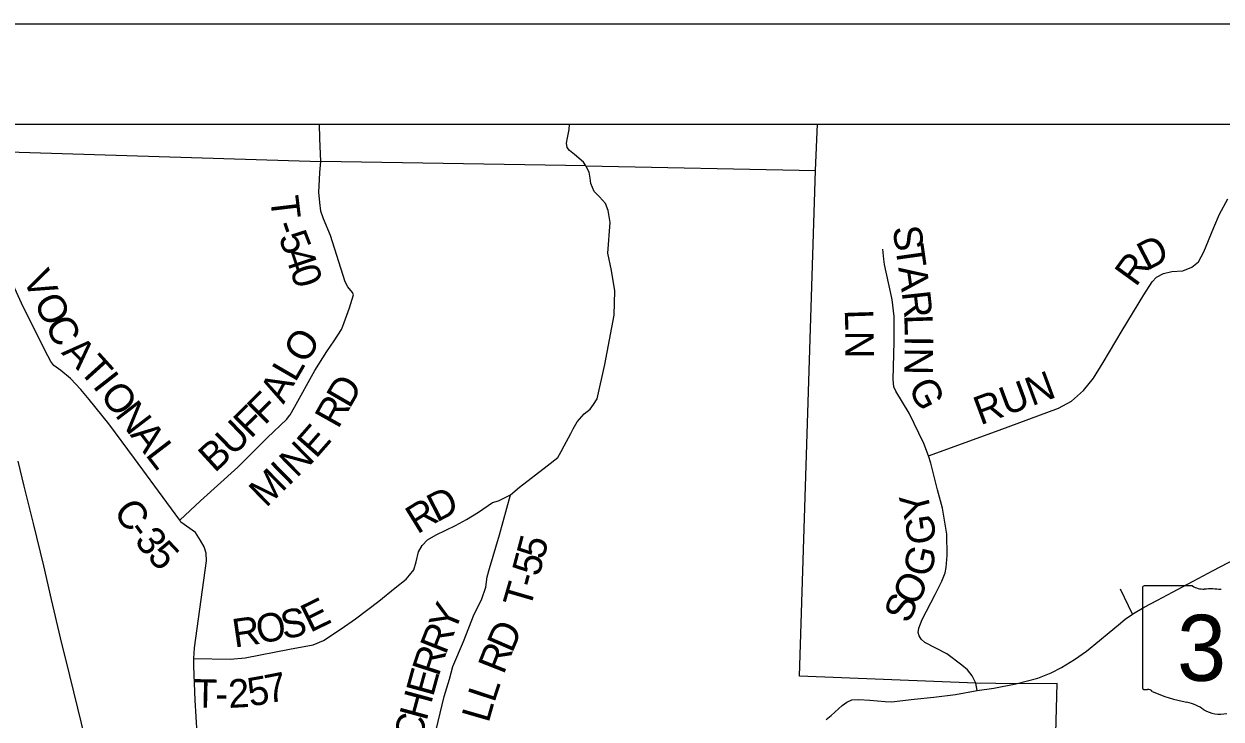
# Model space of a CAD drawing. Extents: x -22 to 431, y -18 to 160.
# Drawn here: x 324.836 to 327.228, y 158.732 to 160.12 of the extents above; entities that cross this region are included whole.
import ezdxf

# ---------------------------------------------------------------- set-up
doc = ezdxf.new("R2010")
doc.units = 0
for name, color, linetype in [('GM_X_Adjacent_County_Text', 7, 'Continuous'), ('GM_X_Airport_Location_Class_2', 7, 'Continuous'), ('GM_X_City_Street', 7, 'Continuous'), ('GM_X_City_Street_Text', 7, 'Continuous'), ('GM_X_County_ROW', 7, 'Continuous'), ('GM_X_Major_River_Text', 7, 'Continuous'), ('GM_X_Minor_River_Text', 7, 'Continuous'), ('GM_X_Rail_Line', 7, 'Continuous'), ('GM_X_Section', 7, 'Continuous')]:
    doc.layers.add(name, color=color, linetype=linetype)

msp = doc.modelspace()

# ---------------------------------------------------------------- linework, layer by layer
at = {"layer": 'GM_X_Adjacent_County_Text'}
for points in [[(325.1477, 159.1289), (325.1213, 159.1641), (325.057, 159.252), (325.0057, 159.3213), (324.9662, 159.3699), (324.9498, 159.3902), (324.9293, 159.4116), (324.9095, 159.4278), (324.896, 159.4378), (324.8897, 159.4458), (324.8837, 159.4573), (324.8346, 159.5549), (324.8044, 159.6209), (324.7775, 159.6781), (324.7754, 159.6876), (324.7699, 159.7066), (324.7645, 159.7613), (324.7657, 159.7999), (324.7685, 159.8633)], [(325.2014, 158.1784), (325.2032, 158.2202), (325.2052, 158.2656), (325.2047, 158.3058), (325.2054, 158.3188), (325.2013, 158.3826), (325.196, 158.4523), (325.1937, 158.5182), (325.1897, 158.5964), (325.1838, 158.6696), (325.1784, 158.7696), (325.1754, 158.8374), (325.1757, 158.8531), (325.1766, 158.8743), (325.2008, 159.0478), (325.2, 159.063), (325.1962, 159.0756), (325.189, 159.0885), (325.1787, 159.1045), (325.1495, 159.1247), (325.1477, 159.1289)]]:
    msp.add_lwpolyline(points, dxfattribs=at)
at = {"layer": 'GM_X_Airport_Location_Class_2'}
for p, q in [((327.0707, 158.9942), (327.0707, 158.7941)), ((327.1705, 158.9977), (327.074, 158.9977))]:
    msp.add_line(p, q, dxfattribs=at)
for centre, major_axis, start_param, end_param in [((327.0745, 158.9947), (0.00382, 0), 1.712693, 3.28349), ((327.1935, 159.0209), (0.037, 0), 4.042523, 4.731795), ((327.2058, 158.8853), (0.133, 0), 1.404758, 1.657858), ((327.0745, 158.7937), (0.00385, 0), 3.00124, 4.508301), ((327.0751, 158.8141), (0.0294, 0), 4.665946, 4.897461), ((327.0811, 158.7826), (0.0106, 0), 0.519207, 1.627899), ((327.215, 158.9624), (0.2524, 0), 4.195997, 4.488961), ((327.1397, 158.7042), (0.079, 0), 0.823519, 1.323587), ((327.2251, 158.7816), (0.0501, 0), 4.026481, 4.996735)]:
    msp.add_ellipse(centre, major_axis=major_axis, ratio=0.8, start_param=start_param, end_param=end_param, dxfattribs=at)
at = {"layer": 'GM_X_County_ROW'}
msp.add_lwpolyline([(326.4388, 158.7307), (326.4488, 158.7388), (326.4707, 158.7588), (326.48, 158.7658), (326.4898, 158.7701), (326.5039, 158.7708), (326.5259, 158.7696), (326.5567, 158.7667), (326.57, 158.7661), (326.5859, 158.7683), (326.6143, 158.7714), (326.6537, 158.7755), (326.6972, 158.7808), (326.7405, 158.7888), (326.7735, 158.7934), (326.8175, 158.8019), (326.8618, 158.8135), (326.8882, 158.8242), (326.9088, 158.8347), (326.9351, 158.8511), (326.9588, 158.8675), (326.985, 158.8888), (327.0044, 158.9047), (327.0228, 158.9202), (327.0359, 158.931), (327.0507, 158.9411), (327.0531, 158.9427), (327.0738, 158.9552), (327.1009, 158.969), (327.1309, 158.9854), (327.1723, 159.007), (327.2118, 159.0285), (327.2566, 159.0517)], dxfattribs=at)
at = {"layer": 'GM_X_Major_River_Text'}
for p, q in [((326.4177, 159.8276), (326.4213, 159.9199)), ((324.7687, 159.8658), (325.4291, 159.8451)), ((325.9586, 159.8363), (325.4291, 159.8451)), ((325.9586, 159.8363), (326.4177, 159.8276)), ((326.3856, 158.8174), (326.4177, 159.8276)), ((326.7375, 158.8037), (326.3856, 158.8174)), ((326.8175, 158.8019), (326.7375, 158.8037)), ((326.9, 158.8029), (326.8175, 158.8019)), ((326.869, 157.4312), (326.9, 158.8029))]:
    msp.add_line(p, q, dxfattribs=at)
at = {"layer": 'GM_X_Minor_River_Text'}
for points in [[(325.4274, 159.8231), (325.4291, 159.8451), (325.4271, 159.8915), (325.4267, 159.9199)], [(325.9244, 159.9061), (325.9251, 159.9094), (325.926, 159.9199)], [(325.9156, 159.2774), (325.9288, 159.3022), (325.9331, 159.3113), (325.9415, 159.3257), (325.9555, 159.3411), (325.9674, 159.3507), (325.9742, 159.3598), (325.981, 159.3716), (325.9969, 159.4398), (326.0151, 159.5381), (326.0169, 159.5867), (326.0099, 159.6277), (326.0026, 159.6622), (326.0071, 159.7232), (326.0035, 159.7477), (325.9981, 159.7614), (325.9862, 159.775), (325.9754, 159.7853), (325.9688, 159.801), (325.9674, 159.8118), (325.9652, 159.8242), (325.9586, 159.8363), (325.954, 159.8439), (325.9357, 159.8591), (325.9257, 159.8674), (325.9211, 159.8735), (325.9202, 159.882), (325.9217, 159.8924), (325.9244, 159.9061)], [(325.3675, 159.3392), (325.3677, 159.3395), (325.3765, 159.3548), (325.417, 159.4282), (325.441, 159.4658), (325.4556, 159.4874), (325.4706, 159.5099), (325.4733, 159.5167), (325.4863, 159.5528), (325.4942, 159.5789), (325.4923, 159.5839), (325.4832, 159.5952), (325.4775, 159.605), (325.4486, 159.6978), (325.4346, 159.7307), (325.429, 159.7458), (325.4275, 159.7632), (325.4252, 159.7843), (325.4263, 159.8096), (325.4274, 159.8231)], [(326.7405, 158.7888), (326.7375, 158.8037), (326.7305, 158.818), (326.721, 158.8301), (326.7101, 158.8392), (326.6801, 158.8624), (326.6361, 158.8845), (326.6286, 158.8911), (326.6245, 158.8979), (326.6227, 158.9048), (326.6239, 158.9131), (326.6309, 158.9309), (326.6567, 158.9803), (326.6698, 159.0071), (326.6764, 159.0241), (326.6788, 159.0347), (326.6805, 159.0586), (326.6798, 159.1011), (326.6712, 159.1532), (326.6609, 159.1893), (326.6478, 159.243), (326.643, 159.2578), (326.7843, 159.3088), (326.9032, 159.3528), (326.9287, 159.3665), (326.9531, 159.3879), (326.9727, 159.4128), (326.9923, 159.4441), (327.0303, 159.5075), (327.0734, 159.5788), (327.0899, 159.6048), (327.0987, 159.6142), (327.1128, 159.6217), (327.1291, 159.6257), (327.1511, 159.627), (327.1693, 159.634), (327.183, 159.6452), (327.1931, 159.6649), (327.2132, 159.7136), (327.2248, 159.7401), (327.2414, 159.7707)], [(326.643, 159.2578), (326.6338, 159.2822), (326.6044, 159.3425), (326.5779, 159.3868), (326.5738, 159.3951), (326.5728, 159.4096), (326.5747, 159.4851), (326.5747, 159.5356), (326.5705, 159.5698), (326.5585, 159.6242), (326.5556, 159.6398), (326.5538, 159.65), (326.5521, 159.6702)], [(325.1477, 159.1289), (325.1891, 159.1673), (325.2636, 159.235), (325.3219, 159.2932), (325.3611, 159.3305), (325.3667, 159.3378), (325.3675, 159.3392)], [(325.6257, 158.5856), (325.6274, 158.5922), (325.6327, 158.6116), (325.6594, 158.7102), (325.6757, 158.7766), (325.686, 158.8114), (325.6926, 158.8365), (325.7141, 158.8867), (325.7356, 158.9415), (325.75, 158.9697), (325.7587, 158.9953), (325.7618, 159.0158), (325.7659, 159.0327), (325.7862, 159.1), (325.8084, 159.1795), (325.8259, 159.1952), (325.8817, 159.2373), (325.9028, 159.2543), (325.9094, 159.2659), (325.9156, 159.2774)], [(325.1757, 158.8531), (325.248, 158.8517), (325.2783, 158.854), (325.3663, 158.8713), (325.4139, 158.8802), (325.4342, 158.8889), (325.4696, 158.9118), (325.4986, 158.9323), (325.5448, 158.9673), (325.5776, 158.9936), (325.5995, 159.0112), (325.6066, 159.0189), (325.6148, 159.0301), (325.6194, 159.046), (325.624, 159.0655), (325.6317, 159.0783), (325.642, 159.0895), (325.6599, 159.0998), (325.6984, 159.1182), (325.7205, 159.1305), (325.7439, 159.1447), (325.7723, 159.164), (325.7841, 159.1673), (325.8084, 159.1795)], [(327.0507, 158.9411), (327.0271, 158.9914)]]:
    msp.add_lwpolyline(points, dxfattribs=at)
at = {"layer": 'GM_X_Rail_Line'}
msp.add_lwpolyline([(325.0236, 158.268), (325.0178, 158.3353), (325.0111, 158.3892), (325.0083, 158.4105), (325.0062, 158.4257), (324.9949, 158.5051), (324.9839, 158.5695), (324.9706, 158.6339), (324.9581, 158.6937), (324.9437, 158.7535), (324.9274, 158.819), (324.909, 158.8939), (324.8914, 158.9704), (324.8757, 159.0378), (324.855, 159.1222), (324.8366, 159.1967), (324.8245, 159.247)], dxfattribs=at)
at = {"layer": 'GM_X_Section'}
msp.add_line((319.5549, 159.9199), (331.7949, 159.9199), dxfattribs=at)
msp.add_lwpolyline([(319.3549, 160.1199), (331.9949, 160.1199), (331.9949, 147.4799), (319.3549, 147.4799)], close=True, dxfattribs=at)

# ---------------------------------------------------------------- texts
at = {"layer": 'GM_X_Airport_Location_Class_2'}
msp.add_text('313', height=0.13184, dxfattribs=at).set_placement((327.1398, 158.8082))
at = {"layer": 'GM_X_City_Street'}
for s, rotation, p in [('V', 294.5617, (324.833, 159.6124)), ('O', 296.2146, (324.8546, 159.5653)), ('C', 296.7147, (324.8769, 159.5199)), ('A', 314.6749, (324.9092, 159.4625)), ('T', 312.1791, (324.9439, 159.4274)), ('I', 308.0588, (324.9717, 159.3968)), ('O', 307.4906, (324.986, 159.3785)), ('N', 307.4491, (325.0165, 159.3389)), ('A', 307.4477, (325.0469, 159.2992)), ('L', 307.4493, (325.0773, 159.2595)), ('C', 305.6357, (325.013, 159.1461)), ('-', 306.0104, (325.0404, 159.1079)), ('3', 307.5967, (325.0552, 159.0876)), ('5', 313.2597, (325.0805, 159.0552))]:
    msp.add_text(s, height=0.0568, rotation=rotation, dxfattribs=at).set_placement(p)
at = {"layer": 'GM_X_City_Street_Text'}
for s, height, rotation, p in [('T', 0.0568, 276.7915, (325.3276, 159.7734)), ('-', 0.0568, 288.9884, (325.3355, 159.7184)), ('5', 0.0568, 291.0715, (325.3439, 159.6942)), ('S', 0.0568, 278.114, (326.5713, 159.7135)), ('D', 0.0568, 27.4415, (327.0796, 159.6265)), ('T', 0.0568, 278.1141, (326.5767, 159.6756)), ('4', 0.0568, 288.3543, (325.3562, 159.6622)), ('R', 0.0568, 54.1055, (327.0575, 159.5932)), ('0', 0.0568, 287.5883, (325.3672, 159.6292)), ('A', 0.0568, 278.0884, (326.5827, 159.6335)), ('R', 0.0568, 276.1984, (326.5897, 159.5845)), ('L', 0.0568, 271.7959, (326.4758, 159.5491)), ('L', 0.0568, 271.826, (326.5947, 159.5392)), ('O', 0.0568, 57.676, (325.3991, 159.439)), ('N', 0.0568, 270.0838, (326.4772, 159.507)), ('I', 0.0568, 269.3521, (326.596, 159.4974)), ('N', 0.0568, 269.2896, (326.5957, 159.4741)), ('L', 0.0568, 59.9186, (325.3781, 159.4027)), ('A', 0.0568, 61.8228, (325.3547, 159.3591)), ('D', 0.0568, 59.8665, (325.4865, 159.3501)), ('G', 0.0568, 296.4559, (326.6016, 159.3957)), ('RUN', 0.05682, 20.3691, (326.7469, 159.3182)), ('F', 0.0568, 44.9839, (325.3168, 159.3174)), ('F', 0.0568, 44.5069, (325.2891, 159.2902)), ('R', 0.0568, 60.6874, (325.4637, 159.3096)), ('U', 0.0568, 44.16, (325.2529, 159.2551)), ('E', 0.0568, 48.6437, (325.4193, 159.2504)), ('B', 0.0568, 42.5181, (325.2172, 159.2223)), ('N', 0.0568, 44.6517, (325.3808, 159.2121)), ('I', 0.0568, 44.3919, (325.3639, 159.1956)), ('M', 0.0568, 44.3358, (325.3198, 159.1524)), ('R', 0.0568, 31.679, (325.6219, 159.1001)), ('D', 0.0568, 27.0994, (325.6605, 159.124)), ('Y', 0.0568, 104.8598, (326.6512, 159.1418)), ('G', 0.0568, 97.9858, (326.6596, 159.085)), ('5', 0.0568, 75.1994, (325.8742, 159.0486)), ('G', 0.0568, 76.4737, (326.6468, 159.0133)), ('5', 0.0568, 75.147, (325.8652, 159.0147)), ('T', 0.0568, 73.8085, (325.8469, 158.95)), ('-', 0.0568, 74.9934, (325.8591, 158.992)), ('O', 0.0568, 62.7613, (326.6187, 158.9549)), ('S', 0.0568, 66.8176, (326.6041, 158.9206)), ('S', 0.0568, 11.0136, (325.3548, 158.891)), ('E', 0.0568, 26.2466, (325.408, 158.9036)), ('Y', 0.0568, 67.6973, (325.6956, 158.9019)), ('R', 0.0568, 8.3233, (325.2567, 158.8745)), ('O', 0.0568, 10.7528, (325.3054, 158.8817)), ('R', 0.0568, 68.4254, (325.6785, 158.8586)), ('D', 0.0568, 66.5431, (325.8113, 158.8621)), ('R', 0.0568, 68.5682, (325.7944, 158.8192)), ('R', 0.0568, 71.8866, (325.6643, 158.8151)), ('E', 0.0568, 74.6015, (325.6533, 158.7748)), ('T', 0.0568, 358.7206, (325.1751, 158.755)), ('2', 0.0568, 3.0786, (325.2456, 158.7539)), ('5', 0.0568, 9.9223, (325.2879, 158.7566)), ('7', 0.0568, 10.957, (325.3235, 158.7629)), ('H', 0.0568, 74.9163, (325.6403, 158.7266)), ('L', 0.0568, 71.8259, (325.7758, 158.763)), ('-', 0.0568, 359.3924, (325.2183, 158.7541)), ('L', 0.0568, 73.9869, (325.7642, 158.7227)), ('C', 0.0568, 74.9172, (325.6281, 158.6816))]:
    msp.add_text(s, height=height, rotation=rotation, dxfattribs=at).set_placement(p)

doc.saveas('drawing.dxf')
